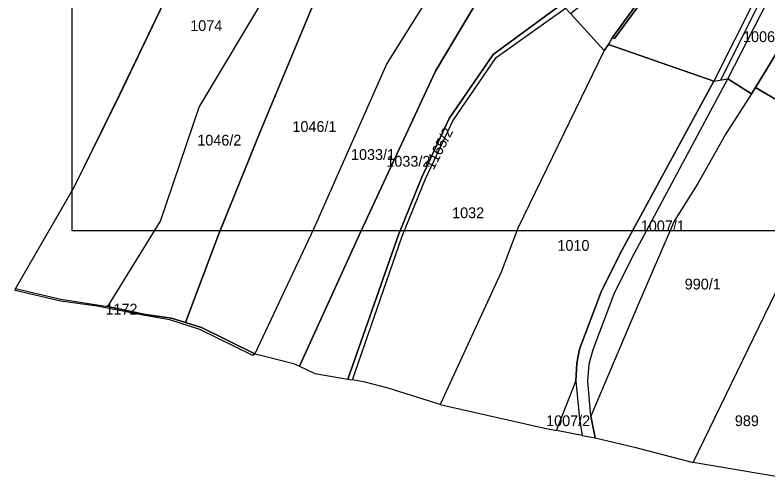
# Model space of a CAD drawing. Extents: x -623250 to -619626, y -1079612 to -1075424.
# Drawn here: x -622820 to -622122, y -1079469 to -1079039 of the extents above; entities that cross this region are included whole.
import ezdxf

# ---------------------------------------------------------------- set-up
doc = ezdxf.new("R2010")
doc.units = 0
for name, color, linetype in [('Hranice šetřená (k_ú_Džbánov - vnitřní obvod)', 7, 'Continuous'), ('Katastrální hranice', 7, 'Continuous'), ('Parcela nároku', 7, 'Continuous'), ('Parcelní číslo', 7, 'Continuous'), ('Pomocné k tisku', 7, 'Continuous'), ('Silnice III_35719', 7, 'Continuous')]:
    doc.layers.add(name, color=color, linetype=linetype)

msp = doc.modelspace()

# ---------------------------------------------------------------- linework, layer by layer
at = {"layer": 'Hranice šetřená (k_ú_Džbánov - vnitřní obvod)'}
msp.add_lwpolyline([(-622304.92, -1079037.85), (-622273.51, -1079072.09), (-622269.66, -1079066.41), (-622171.75, -1079100.51), (-622158.74, -1079098.38), (-622136.82, -1079112.45), (-622133.2, -1079106.32), (-622055.86, -1079151.87)], dxfattribs=at)
at = {"layer": 'Katastrální hranice'}
for p, q in [((-622682.13, -1079027.65), (-622723.41, -1079113.68)), ((-622723.41, -1079113.68), (-622765.39, -1079198.72)), ((-622765.39, -1079198.72), (-622788.9, -1079239.36))]:
    msp.add_line(p, q, dxfattribs=at)
at = {"layer": 'Parcela nároku'}
for points in [[(-622765.48, -1079198.57), (-622819.87, -1079292.93), (-622777.71, -1079303.04), (-622734.33, -1079309.65), (-622685.22, -1079230.66), (-622649.57, -1079124.65), (-622584.41, -1079015.93), (-622549.92, -1078964.99), (-622504.04, -1078882.08), (-622531.63, -1078867.83), (-622564.18, -1078846.05), (-622560.49, -1078827.83), (-622571.06, -1078841.41), (-622574.17, -1078840.81), (-622662.09, -1078987.1), (-622682.23, -1079027.29), (-622723.63, -1079113.57)], [(-622200, -1078950.05), (-622157.65, -1078929.82), (-622138.45, -1078908.72), (-622109.45, -1078890.7), (-622079.99, -1078876.08), (-622055.18, -1078868.03), (-622113.39, -1078984.18), (-622171.75, -1079100.51), (-622269.66, -1079066.41), (-622266.09, -1079060.25), (-622264, -1079060.86), (-622230.39, -1079014.76), (-622211.8, -1078982.44)], [(-622413.78, -1078894.82), (-622405.61, -1078910.27), (-622383.93, -1078928.74), (-622392.23, -1078946.58), (-622401.23, -1078965.91), (-622475.14, -1079084.13), (-622543.14, -1079237.22), (-622597.76, -1079353.55), (-622647.35, -1079329.22), (-622662.1, -1079324.57), (-622631.29, -1079242.39), (-622592.92, -1079147.49), (-622524.64, -1078984.09), (-622503.13, -1079003.12), (-622481.9, -1079021.9), (-622449.19, -1078968.22)], [(-622202.14, -1078951.24), (-622200, -1078950.05), (-622211.8, -1078982.44), (-622230.39, -1079014.76), (-622264, -1079060.86), (-622266.09, -1079060.25), (-622232.67, -1079014.18), (-622215.51, -1078984.39)], [(-622265.74, -1078997.47), (-622231.77, -1078967.76), (-622202.14, -1078951.24), (-622215.51, -1078984.39), (-622232.67, -1079014.18), (-622266.09, -1079060.25), (-622269.66, -1079066.41), (-622273.51, -1079072.09), (-622304.92, -1079037.85), (-622288.27, -1079024.59)], [(-622549.92, -1078964.99), (-622524.64, -1078984.09), (-622592.92, -1079147.49), (-622631.29, -1079242.39), (-622662.1, -1079324.57), (-622675.17, -1079320.45), (-622699.27, -1079317.02), (-622734.33, -1079309.65), (-622685.22, -1079230.66), (-622649.57, -1079124.65), (-622584.41, -1079015.93)], [(-622475.14, -1079084.13), (-622543.14, -1079237.22), (-622597.76, -1079353.55), (-622589.71, -1079355.56), (-622561.74, -1079362.54), (-622556.4, -1079365.13), (-622499.53, -1079240.2), (-622430.15, -1079091.4), (-622376.61, -1079001.16), (-622401.23, -1078965.91)], [(-622430.15, -1079091.4), (-622499.53, -1079240.2), (-622556.4, -1079365.13), (-622542.15, -1079372.02), (-622511.38, -1079377.16), (-622464.39, -1079243.21), (-622442.64, -1079189.54), (-622417.34, -1079135.36), (-622376.52, -1079075.69), (-622312.46, -1079028.67), (-622328.59, -1079007.13), (-622357.91, -1079027.95), (-622376.61, -1079001.16)], [(-622158.74, -1079098.38), (-622110.04, -1079002.85), (-622075.29, -1079015.62), (-622092.87, -1079040.63), (-622133.2, -1079106.32), (-622136.82, -1079112.45)], [(-622464.39, -1079243.21), (-622511.38, -1079377.16), (-622507.06, -1079377.88), (-622461.05, -1079244.56), (-622439.52, -1079191.32), (-622413.95, -1079137.32), (-622373.84, -1079078.54), (-622309.54, -1079032.81), (-622312.46, -1079028.67), (-622376.52, -1079075.69), (-622417.34, -1079135.36), (-622442.64, -1079189.54)], [(-622413.95, -1079137.32), (-622373.84, -1079078.54), (-622309.54, -1079032.81), (-622304.92, -1079037.85), (-622273.51, -1079072.09), (-622353.54, -1079237.05), (-622369.17, -1079277.84), (-622425.88, -1079400.76), (-622474.05, -1079385.38), (-622495.27, -1079379.85), (-622507.06, -1079377.88), (-622461.05, -1079244.56), (-622439.52, -1079191.32)], [(-622133.2, -1079106.32), (-622092.87, -1079040.63), (-622091.59, -1079044.45), (-622055.86, -1079151.87)], [(-622273.51, -1079072.09), (-622353.54, -1079237.05), (-622369.17, -1079277.84), (-622425.88, -1079400.76), (-622415.08, -1079403.19), (-622330.22, -1079422.3), (-622325.56, -1079423.22), (-622317.67, -1079424.78), (-622299.93, -1079379.12), (-622298.83, -1079362.19), (-622296.43, -1079349.35), (-622276.32, -1079295.98), (-622258.58, -1079260.39), (-622171.75, -1079100.51), (-622269.66, -1079066.41)], [(-622247.92, -1079264.75), (-622158.74, -1079098.38), (-622136.82, -1079112.45), (-622160.78, -1079149.39), (-622186.54, -1079195.45), (-622208.62, -1079230.51), (-622242.74, -1079309.34), (-622285.94, -1079411.42), (-622288.69, -1079379.11), (-622287.33, -1079363.06), (-622283.79, -1079349.54), (-622264.39, -1079297.94)], [(-622242.74, -1079309.34), (-622285.94, -1079411.42), (-622281.85, -1079431.73), (-622245.27, -1079440.23), (-622232.32, -1079443.63), (-622191.02, -1079454.47), (-622109.37, -1079286.11), (-622053.55, -1079157.48), (-622055.86, -1079151.87), (-622133.2, -1079106.32), (-622136.82, -1079112.45), (-622160.78, -1079149.39), (-622186.54, -1079195.45), (-622208.62, -1079230.51)], [(-622108.69, -1079439.45), (-622106.8, -1079468.8), (-622191.02, -1079454.47), (-622109.37, -1079286.11), (-622113.01, -1079308.51), (-622111.25, -1079336.82), (-622105.41, -1079382.94)], [(-622675.17, -1079320.45), (-622662.1, -1079324.57), (-622647.35, -1079329.22), (-622597.76, -1079353.55), (-622599.49, -1079355.07), (-622648.79, -1079330.97), (-622676.68, -1079322.03), (-622699.75, -1079317.96), (-622744.24, -1079309.43), (-622777.91, -1079304.6), (-622820.32, -1079294.87), (-622819.87, -1079292.93), (-622777.71, -1079303.04), (-622734.33, -1079309.65), (-622699.27, -1079317.02)], [(-622296.33, -1079413.72), (-622294.07, -1079429.45), (-622317.67, -1079424.78), (-622299.93, -1079379.12)]]:
    msp.add_lwpolyline(points, close=True, dxfattribs=at)
msp.add_lwpolyline([(-622113.39, -1078984.18), (-622171.75, -1079100.51), (-622258.58, -1079260.39), (-622276.32, -1079295.98), (-622296.43, -1079349.35), (-622298.83, -1079362.19), (-622299.93, -1079379.12), (-622296.33, -1079413.72), (-622294.07, -1079429.45), (-622281.85, -1079431.73), (-622285.94, -1079411.42), (-622288.69, -1079379.11), (-622287.33, -1079363.06), (-622283.79, -1079349.54), (-622264.39, -1079297.94), (-622247.92, -1079264.75), (-622158.74, -1079098.38), (-622110.04, -1079002.85)], dxfattribs=at)
at = {"layer": 'Pomocné k tisku'}
msp.add_lwpolyline([(-622767.31, -1075424.03), (-619626.32, -1075424.03), (-619626.32, -1079239.36), (-622767.31, -1079239.36)], close=True, dxfattribs=at)
at = {"layer": 'Silnice III_35719'}
msp.add_line((-622165.24, -1079099.44), (-622009.59, -1078788.2), dxfattribs=at)

# ---------------------------------------------------------------- texts
at = {"layer": 'Parcelní číslo'}
for s, p in [('1074', (-622657.75, -1079054.06)), ('1006/2', (-622144.67, -1079064.31)), ('1046/1', (-622562.9, -1079147.71)), ('1046/2', (-622651.2, -1079160.35)), ('1033/1', (-622508.53, -1079173.69)), ('1033/2', (-622475.72, -1079179.94)), ('1032', (-622414.68, -1079227.75)), ('1007/1', (-622239.55, -1079239.88)), ('1010', (-622316.93, -1079257.98)), ('990/1', (-622198.78, -1079293.89)), ('1172', (-622736.45, -1079317.14)), ('1007/2', (-622327.42, -1079420.7)), ('989', (-622152.29, -1079420.7))]:
    msp.add_text(s, height=10, dxfattribs=at).set_placement(p)
msp.add_text('1165/2', height=10, rotation=63.16452, dxfattribs=at).set_placement((-622431.83, -1079183.47))

doc.saveas('drawing.dxf')
